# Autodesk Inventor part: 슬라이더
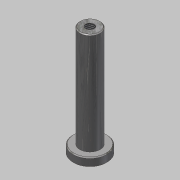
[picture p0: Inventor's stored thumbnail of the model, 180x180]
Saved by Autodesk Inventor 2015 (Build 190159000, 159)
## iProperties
Created: 2016-02
Part Number: 슬라이더
Material: 스테인리스강
Document SubType Name: Modeling
Designer: mduedu
Density: 8.08 g/cm^3
Mass: 65.4431 g
Surface Area: 33.4413 cm^2
Volume: 8.0994 cm^3
Appearance: 반광택
Author: mduedu
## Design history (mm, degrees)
sketch "스케치1"
  geometry: C1 r 10 at (0, 0); 1 further point
  constraints: 1 centre point, 1 coincident
  dimensions: "d0" = 20 diameter of C1
extrude "돌출1" new body sketch "스케치1" distance "d1" = 5; taper "d2" = 0 deg
sketch "스케치2"
  geometry: C1 r 6 at (0, 0); 1 further point
  constraints: 1 centre point, 1 coincident
  dimensions: "d3" = 12 diameter of C1
extrude "돌출2" join sketch "스케치2" distance "d4" = 60; taper "d5" = 0 deg
chamfer "모따기1" distance "d6" = 0.5; stored, may be unused: second distance "d7" = 2, angle "d8" = 45 deg
hole "구멍1" diameter "d11" = 4.917; stored, may be unused: countersink angle "d15" = 90 deg, drill point angle "d17" = 118 deg; dims "d9" = 10, "d10" = 10, "d12" = 10, "d13" = 4, "d14" = 2, "d16" = 12
chamfer "모따기2" distance "d18" = 0.5; stored, may be unused: second distance "d19" = 2, angle "d20" = 45 deg
node "솔리드1"
